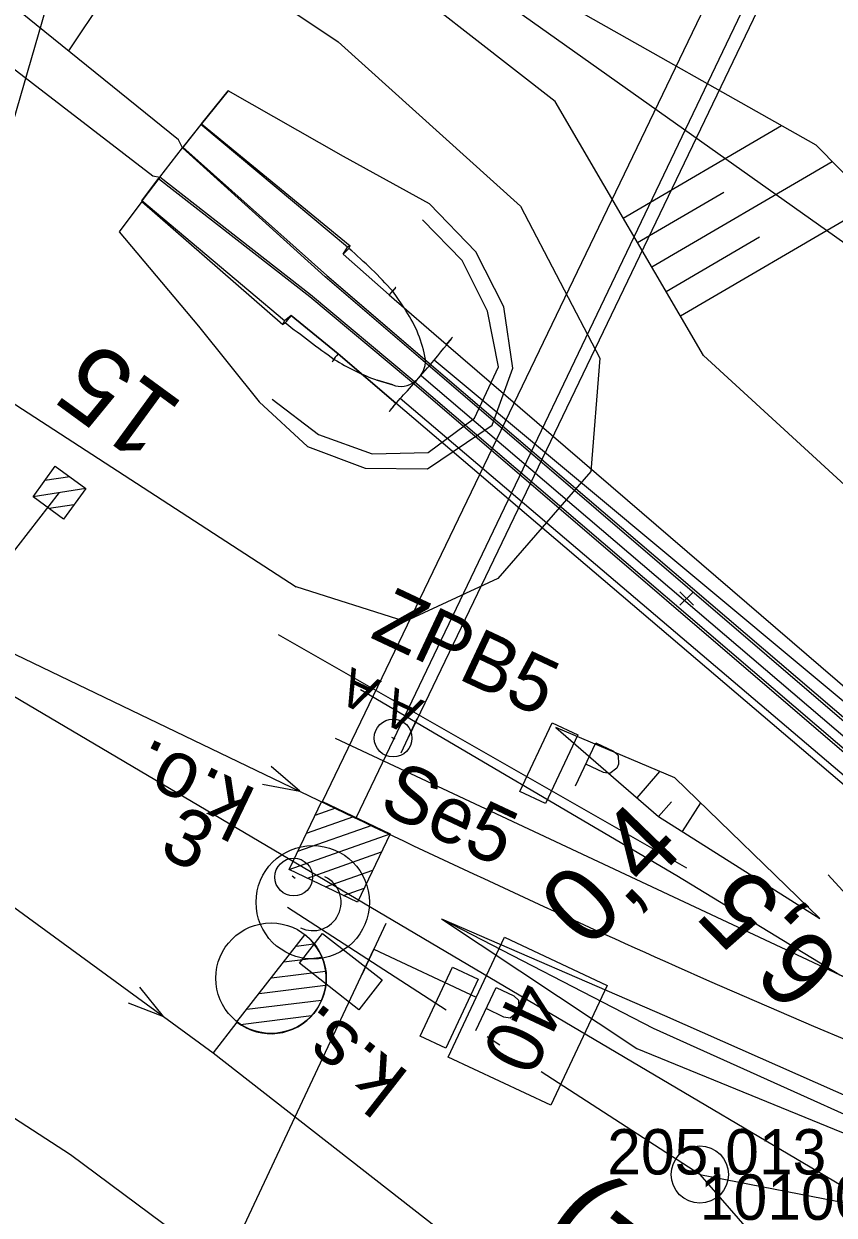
# Model space of a CAD drawing. Extents: x -800194 to -799078, y -1007177 to -1006597.
# Drawn here: x -799787.92 to -799766.47, y -1006976.93 to -1006945.41 of the extents above; entities that cross this region are included whole.
import ezdxf

# ---------------------------------------------------------------- set-up
doc = ezdxf.new("R2010")
doc.units = 0
for name, color, linetype in [('02_Osa_koleje', 7, 'Continuous'), ('_návrh', 7, 'Continuous'), ('_popvyt', 7, 'Continuous'), ('Vrstva 11', 7, 'Continuous'), ('Vrstva 13', 7, 'Continuous'), ('Vrstva 16', 7, 'Continuous'), ('Vrstva 17', 7, 'Continuous'), ('Vrstva 18', 7, 'Continuous'), ('Vrstva 2', 7, 'Continuous'), ('Vrstva 25', 7, 'Continuous'), ('Vrstva 27', 7, 'Continuous'), ('Vrstva 3', 7, 'Continuous'), ('Vrstva 34', 7, 'Continuous'), ('Vrstva 36', 7, 'Continuous'), ('Vrstva 4', 7, 'Continuous'), ('Vrstva 48', 7, 'Continuous'), ('Vrstva 49', 7, 'Continuous'), ('Vrstva 5', 7, 'Continuous'), ('Vrstva 55', 7, 'Continuous'), ('Vrstva 6', 7, 'Continuous'), ('Vrstva 60', 7, 'Continuous'), ('Vrstva 61', 7, 'Continuous'), ('Vrstva 63', 7, 'Continuous')]:
    doc.layers.add(name, color=color, linetype=linetype)

msp = doc.modelspace()

# ---------------------------------------------------------------- linework, layer by layer
at = {"layer": '02_Osa_koleje'}
msp.add_lwpolyline([(-799770.682, -1006970.328), (-799769.768, -1006970.733), (-799768.852, -1006971.134), (-799767.934, -1006971.532), (-799767.016, -1006971.927), (-799766.096, -1006972.319), (-799765.175, -1006972.709), (-799764.252, -1006973.095), (-799763.329, -1006973.478), (-799762.404, -1006973.858), (-799761.478, -1006974.235), (-799760.55, -1006974.609), (-799759.621, -1006974.98), (-799758.692, -1006975.348), (-799757.761, -1006975.713), (-799756.828, -1006976.075), (-799755.895, -1006976.434), (-799754.96, -1006976.789), (-799754.025, -1006977.142)], dxfattribs=at)
msp.add_arc((-799645.745, -1006688.806), 308, 244.32513, 246.06876, dxfattribs=at)
at = {"layer": '_návrh'}
msp.add_line((-799791.14, -1006960.652), (-799779.191, -1006966.397), dxfattribs=at)
for points in [[(-799821.595, -1006948.007), (-799811.064, -1006954.324), (-799803.753, -1006958.707), (-799793.935, -1006964.581), (-799784.224, -1006971.671), (-799782.913, -1006972.63), (-799767.418, -1006984.719), (-799752.333, -1006998.173), (-799735.027, -1007015.997), (-799721.623, -1007030.81), (-799713.555, -1007039.726), (-799713.111, -1007040.218)], [(-799820.755, -1006954.001), (-799803.004, -1006964.743), (-799786.682, -1006975.322), (-799769.882, -1006987.807), (-799754.745, -1007000.643), (-799736.311, -1007017.261), (-799721.623, -1007030.81)]]:
    msp.add_lwpolyline(points, dxfattribs=at)
msp.add_circle((-799780.274, -1006968.65), 1.5, dxfattribs=at)
for start, end in [(334.3251, 64.3251), (244.3251, 334.3251)]:
    msp.add_arc((-799780.274, -1006968.65), 0.75, start, end, dxfattribs=at)
at = {"layer": 'Vrstva 11'}
for p, q in [((-799786.705, -1006957.392), (-799787.366, -1006957.495)), ((-799801.01, -1006975.832), (-799786.978, -1006957.812)), ((-799786.281, -1006957.705), (-799787.674, -1006957.923)), ((-799786.594, -1006958.133), (-799787.246, -1006958.235))]:
    msp.add_line(p, q, dxfattribs=at)
msp.add_lwpolyline([(-799786.869, -1006958.511), (-799787.677, -1006957.921), (-799787.087, -1006957.113), (-799786.279, -1006957.703)], close=True, dxfattribs=at)
at = {"layer": 'Vrstva 16'}
for p, q in [((-799783.217, -1006948.059), (-799782.509, -1006947.186)), ((-799783.233, -1006948.077), (-799783.722, -1006948.693)), ((-799784.321, -1006949.462), (-799783.722, -1006948.693)), ((-799784.321, -1006949.462), (-799784.796, -1006950.091)), ((-799784.795, -1006950.113), (-799785.4, -1006950.909)), ((-799778.158, -1006952.483), (-799777.802, -1006953.01)), ((-799778.157, -1006954.96), (-799778.565, -1006954.841))]:
    msp.add_line(p, q, dxfattribs=at)
for points in [[(-799785.4, -1006950.909), (-799783.301, -1006953.407), (-799781.69, -1006955.406), (-799780.41, -1006956.591), (-799778.888, -1006957.162), (-799777.239, -1006957.179), (-799775.528, -1006956.024), (-799774.978, -1006954.519), (-799775.211, -1006952.901), (-799775.953, -1006951.439), (-799777.187, -1006950.172), (-799779.455, -1006948.919), (-799782.509, -1006947.186)], [(-799779.465, -1006951.506), (-799779.351, -1006951.322), (-799783.233, -1006948.077), (-799783.217, -1006948.059), (-799779.283, -1006951.287)], [(-799783.233, -1006948.077), (-799783.708, -1006948.669), (-799783.722, -1006948.693)], [(-799726.857, -1006999.659), (-799736.574, -1006991.623), (-799742.439, -1006986.725), (-799754.518, -1006974.879), (-799763.734, -1006965.993), (-799777.293, -1006954.374), (-799779.945, -1006952.099), (-799783.722, -1006948.693)], [(-799783.708, -1006948.669), (-799779.9, -1006952.065), (-799777.252, -1006954.333), (-799763.672, -1006965.935), (-799754.476, -1006974.829), (-799742.393, -1006986.703), (-799736.524, -1006991.578), (-799726.778, -1006999.642)], [(-799784.796, -1006950.091), (-799784.356, -1006949.5), (-799784.321, -1006949.462)], [(-799784.356, -1006949.5), (-799780.347, -1006952.62), (-799777.716, -1006954.827), (-799764.168, -1006966.436), (-799754.935, -1006975.363), (-799742.857, -1006987.188), (-799736.94, -1006992.081), (-799727.324, -1007000.028)], [(-799727.258, -1006999.988), (-799736.887, -1006992.032), (-799742.859, -1006987.132), (-799754.894, -1006975.337), (-799764.135, -1006966.374), (-799777.698, -1006954.783), (-799780.331, -1006952.581), (-799784.321, -1006949.462)], [(-799780.843, -1006953.125), (-799781.023, -1006953.264), (-799784.796, -1006950.091)], [(-799784.796, -1006950.091), (-799784.795, -1006950.113), (-799781.066, -1006953.365)], [(-799779.465, -1006951.506), (-799778.251, -1006952.583), (-799776.738, -1006953.884), (-799763.224, -1006965.504), (-799753.999, -1006974.421), (-799741.964, -1006986.204), (-799736.168, -1006991.012), (-799728.577, -1006997.215), (-799726.123, -1006999.163)], [(-799779.316, -1006951.352), (-799779.283, -1006951.287), (-799779.351, -1006951.322)], [(-799780.997, -1006953.316), (-799781.066, -1006953.365), (-799781.023, -1006953.264)], [(-799727.952, -1007000.326), (-799729.82, -1006998.717), (-799737.37, -1006992.486), (-799743.358, -1006987.594), (-799755.401, -1006975.883), (-799764.592, -1006966.926), (-799778.073, -1006955.449), (-799779.598, -1006954.142), (-799780.843, -1006953.125)]]:
    msp.add_lwpolyline(points, dxfattribs=at)
for centre, major_axis, ratio, start_param, end_param in [((-799780.763, -1006952.85), (1.448, 1.499), 0.000154, 0.037167, 0.458976), ((-799789.88, -1006959.484), (14.602, -0.402), 0.815768, 0.661553, 0.784611), ((-799780.886, -1006955.173), (2.894, 2.414), 0.919745, 5.794757, 6.192371), ((-799779.38, -1006951.872), (-1.627, -1.481), 0.054497, 5.778056, 6.111601), ((-799765.39, -1006947.43), (22.33, -7.783), 0.537883, 4.140419, 4.216217), ((-799775.114, -1006948.938), (-6.81, -2.765), 0.83994, 0.550611, 0.741846), ((-799777.883, -1006954.384), (0.368, 0.524), 0.895736, 3.328934, 5.426387)]:
    msp.add_ellipse(centre, major_axis=major_axis, ratio=ratio, start_param=start_param, end_param=end_param, dxfattribs=at)
at = {"layer": 'Vrstva 17'}
msp.add_line((-799766.63, -1006967.927), (-799764.528, -1006970.233), dxfattribs=at)
msp.add_lwpolyline([(-799781.343, -1006955.343), (-799780.121, -1006956.276), (-799778.697, -1006956.784), (-799777.217, -1006956.75), (-799775.995, -1006955.84), (-799775.356, -1006954.486), (-799775.648, -1006953.011), (-799776.321, -1006951.673), (-799777.368, -1006950.593)], dxfattribs=at)
at = {"layer": 'Vrstva 18'}
for p, q in [((-799778.158, -1006952.483), (-799777.802, -1006953.01)), ((-799778.565, -1006954.841), (-799778.157, -1006954.96))]:
    msp.add_line(p, q, dxfattribs=at)
for points in [[(-799779.465, -1006951.506), (-799778.251, -1006952.583), (-799776.738, -1006953.884)], [(-799780.843, -1006953.125), (-799779.598, -1006954.142), (-799778.073, -1006955.449)], [(-799776.738, -1006953.884), (-799763.224, -1006965.504), (-799753.999, -1006974.421), (-799741.964, -1006986.204), (-799736.168, -1006991.012)], [(-799728.689, -1006997.417), (-799736.272, -1006991.186), (-799742.111, -1006986.385), (-799754.178, -1006974.631), (-799763.368, -1006965.72), (-799777.061, -1006954.31)], [(-799736.701, -1006991.694), (-799742.573, -1006986.82), (-799754.68, -1006975.182), (-799763.887, -1006966.256), (-799777.391, -1006954.732)], [(-799737.37, -1006992.486), (-799743.358, -1006987.594), (-799755.401, -1006975.883), (-799764.592, -1006966.926), (-799778.073, -1006955.449)], [(-799729.664, -1006998.596), (-799737.245, -1006992.341), (-799743.186, -1006987.438), (-799755.222, -1006975.72), (-799764.444, -1006966.802), (-799777.959, -1006955.323)]]:
    msp.add_lwpolyline(points, dxfattribs=at)
for centre, major_axis, ratio, start_param, end_param in [((-799780.763, -1006952.85), (1.448, 1.499), 0.000154, 0.037167, 0.458976), ((-799789.88, -1006959.484), (14.602, -0.402), 0.815768, 0.661553, 0.784611), ((-799779.129, -1006954.252), (1.075, 1.846), 0.080877, 0.165328, 0.490733), ((-799779.092, -1006953.855), (1.015, 1.471), 0.015652, 6.081072, 6.66336), ((-799780.886, -1006955.173), (2.894, 2.414), 0.919745, 5.794757, 6.192371), ((-799779.38, -1006951.872), (-1.627, -1.481), 0.054497, 5.778056, 6.111601), ((-799765.39, -1006947.43), (22.33, -7.783), 0.537883, 4.140419, 4.216217), ((-799777.816, -1006955.165), (1.245, 1.471), 0.015308, 5.345189, 6.145729), ((-799777.816, -1006955.216), (1.244, 1.519), 0.010626, 6.159788, 6.793595), ((-799778.587, -1006952.902), (-1.171, -1.446), 0.009799, 6.046537, 6.582716), ((-799777.882, -1006953.279), (-1.858, -1.106), 0.135621, 5.801514, 6.067534), ((-799775.114, -1006948.938), (-6.81, -2.765), 0.83994, 0.550611, 0.741846), ((-799777.883, -1006954.384), (0.368, 0.524), 0.895736, 3.328934, 5.426387), ((-799777.417, -1006954.672), (0.706, 0.807), 0.030898, 3.802387, 5.20436), ((-799777.09, -1006954.29), (-1.161, -1.379), 0.000515, 6.0585, 7.007599), ((-799776.577, -1006954.198), (-1.666, -1.496), 0.062742, 5.768794, 6.060563)]:
    msp.add_ellipse(centre, major_axis=major_axis, ratio=ratio, start_param=start_param, end_param=end_param, dxfattribs=at)
at = {"layer": 'Vrstva 2'}
for p, q in [((-799756.904, -1006917.966), (-799780.025, -1006965.993)), ((-799782.282, -1006971.817), (-799780.481, -1006969.51)), ((-799780.715, -1006969.809), (-799780.242, -1006969.751)), ((-799781.042, -1006970.228), (-799780.034, -1006970.104)), ((-799781.368, -1006970.646), (-799779.935, -1006970.469)), ((-799781.695, -1006971.064), (-799779.932, -1006970.846)), ((-799782.021, -1006971.482), (-799780.038, -1006971.237)), ((-799782.188, -1006971.88), (-799780.304, -1006971.648)), ((-799782.283, -1006971.818), (-799782.913, -1006972.63)), ((-799782.282, -1006971.817), (-799782.282, -1006971.817))]:
    msp.add_line(p, q, dxfattribs=at)
for points in [[(-799781.6, -1006965.523), (-799780.617, -1006965.708), (-799781.376, -1006965.057)], [(-799785.157, -1006971.31), (-799784.224, -1006971.671), (-799784.852, -1006970.892)]]:
    msp.add_lwpolyline(points, dxfattribs=at)
msp.add_circle((-799781.376, -1006970.658), 1.462, dxfattribs=at)
msp.add_arc((-799781.382, -1006970.663), 1.464, 232.0587, 52.0195, dxfattribs=at)
at = {"layer": 'Vrstva 25'}
msp.add_lwpolyline([(-799778.434, -1006970.704), (-799779.049, -1006971.492), (-799780.626, -1006970.262), (-799780.011, -1006969.474), (-799778.434, -1006970.704)], dxfattribs=at)
at = {"layer": 'Vrstva 27'}
for p, q in [((-799778.191, -1006964.283), (-799778.101, -1006964.325)), ((-799780.817, -1006967.954), (-799780.737, -1006968.012))]:
    msp.add_line(p, q, dxfattribs=at)
for centre in [(-799778.146, -1006964.304), (-799780.777, -1006967.983)]:
    msp.add_circle(centre, 0.5, dxfattribs=at)
at = {"layer": 'Vrstva 3'}
for p, q in [((-799756.121, -1006918.343), (-799779.128, -1006966.408)), ((-799780.207, -1006966.345), (-799779.661, -1006966.153)), ((-799780.665, -1006967.302), (-799778.704, -1006966.611)), ((-799780.435, -1006966.823), (-799779.183, -1006966.382)), ((-799780.894, -1006967.78), (-799778.226, -1006966.84)), ((-799780.415, -1006968.009), (-799778.455, -1006967.318)), ((-799779.936, -1006968.238), (-799778.684, -1006967.797)), ((-799779.458, -1006968.467), (-799778.913, -1006968.275))]:
    msp.add_line(p, q, dxfattribs=at)
msp.add_lwpolyline([(-799780.03, -1006965.976), (-799778.226, -1006966.84), (-799779.09, -1006968.644), (-799780.894, -1006967.78)], close=True, dxfattribs=at)
at = {"layer": 'Vrstva 34'}
msp.add_line((-799781.191, -1006961.569), (-799770.384, -1006967.741), dxfattribs=at)
at = {"layer": 'Vrstva 36'}
for points in [[(-799773.933, -1006963.899), (-799773.259, -1006964.216), (-799774.115, -1006966.039), (-799774.789, -1006965.722)], [(-799776.571, -1006970.369), (-799775.897, -1006970.686), (-799776.753, -1006972.509), (-799777.427, -1006972.192)]]:
    msp.add_lwpolyline(points, close=True, dxfattribs=at)
for points in [[(-799773.318, -1006965.568), (-799772.784, -1006964.433), (-799772.312, -1006964.655), (-799772.192, -1006964.77), (-799772.178, -1006965), (-799772.225, -1006965.1), (-799772.413, -1006965.242), (-799772.576, -1006965.215), (-799773.048, -1006964.994)], [(-799775.956, -1006972.038), (-799775.422, -1006970.903), (-799774.95, -1006971.125), (-799774.83, -1006971.24), (-799774.816, -1006971.47), (-799774.863, -1006971.57), (-799775.051, -1006971.712), (-799775.214, -1006971.685), (-799775.686, -1006971.464)]]:
    msp.add_lwpolyline(points, dxfattribs=at)
at = {"layer": 'Vrstva 4'}
for points in [[(-799779.678, -1006964.304), (-799766.319, -1006970.565), (-799761.253, -1006973.176), (-799747.77, -1006978.421), (-799730.774, -1006983.8), (-799710.333, -1006988.709), (-799704.916, -1006989.741), (-799693.131, -1006991.407), (-799682.585, -1006992.929), (-799671.325, -1006993.879), (-799659.363, -1006994.45), (-799648.66, -1006994.501), (-799637.23, -1006994.127), (-799626.066, -1006993.335), (-799614.788, -1006992.17), (-799603.669, -1006990.506), (-799592.467, -1006988.452), (-799581.281, -1006985.916), (-799570.22, -1006982.998), (-799559.296, -1006979.606), (-799542.375, -1006973.485), (-799531.236, -1006968.774), (-799520.48, -1006963.762), (-799510.394, -1006958.536)], [(-799776.864, -1006969.085), (-799770.965, -1006971.646), (-799761.91, -1006975.649), (-799748.544, -1006980.777), (-799731.457, -1006986.215), (-799711.132, -1006991.054), (-799705.482, -1006992.16), (-799693.53, -1006994.084), (-799682.801, -1006995.384), (-799671.514, -1006996.319), (-799659.449, -1006996.851), (-799648.588, -1006996.949), (-799637.262, -1006996.573), (-799625.835, -1006995.773), (-799614.546, -1006994.586), (-799603.199, -1006992.945), (-799591.969, -1006990.857), (-799580.647, -1006988.335), (-799569.534, -1006985.311), (-799558.557, -1006981.947), (-799541.405, -1006975.739), (-799530.263, -1006971.071), (-799519.455, -1006966), (-799509.248, -1006960.724)], [(-799776.864, -1006969.085), (-799771.262, -1006971.982), (-799762.131, -1006976.093), (-799748.706, -1006981.286), (-799731.51, -1006986.353), (-799711.222, -1006991.459), (-799705.527, -1006992.587), (-799693.582, -1006994.543), (-799682.85, -1006995.904), (-799671.5, -1006996.805), (-799659.556, -1006997.356), (-799648.616, -1006997.341), (-799637.276, -1006997.071), (-799625.828, -1006996.297), (-799614.43, -1006995.109), (-799603.18, -1006993.475), (-799591.849, -1006991.264), (-799580.564, -1006988.698), (-799569.449, -1006985.746), (-799558.385, -1006982.386), (-799541.268, -1006976.227), (-799530.102, -1006971.505), (-799519.398, -1006966.36), (-799509.087, -1006961.127)], [(-799779.011, -1006963.023), (-799770.632, -1006967.944), (-799766.319, -1006970.565), (-799761.021, -1006972.82), (-799747.748, -1006977.966), (-799730.719, -1006983.271), (-799710.195, -1006988.108), (-799704.765, -1006989.181), (-799693.072, -1006990.965), (-799682.554, -1006992.238), (-799671.266, -1006993.222), (-799659.388, -1006993.765), (-799648.658, -1006993.824), (-799637.385, -1006993.531), (-799625.769, -1006992.728), (-799614.9, -1006991.542), (-799603.91, -1006989.963), (-799592.572, -1006987.892), (-799581.421, -1006985.419), (-799570.327, -1006982.332), (-799559.429, -1006979.066), (-799542.601, -1006973.013), (-799531.454, -1006968.25), (-799520.744, -1006963.214)], [(-799776.864, -1006969.085), (-799771.693, -1006972.522), (-799762.217, -1006976.394), (-799748.898, -1006981.647), (-799733.68, -1006986.66), (-799728.795, -1006987.945), (-799711.349, -1006992.599), (-799705.744, -1006994.116), (-799693.689, -1006996.09), (-799689.347, -1006996.226), (-799688.222, -1006996.296), (-799683.105, -1006997.407), (-799671.667, -1006998.275)]]:
    msp.add_lwpolyline(points, dxfattribs=at)
at = {"layer": 'Vrstva 48'}
for p, q in [((-799784.426, -1006942.662), (-799786.738, -1006946.125)), ((-799772.055, -1006950.547), (-799767.867, -1006948.1)), ((-799771.298, -1006951.842), (-799766.522, -1006949.052)), ((-799771.676, -1006951.195), (-799769.393, -1006949.861)), ((-799770.541, -1006953.137), (-799765.435, -1006950.154)), ((-799770.919, -1006952.49), (-799768.449, -1006951.046)), ((-799771.688, -1006965.89), (-799771.083, -1006965.192)), ((-799771.121, -1006966.381), (-799770.781, -1006965.989)), ((-799770.486, -1006966.781), (-799770.005, -1006966.018))]:
    msp.add_line(p, q, dxfattribs=at)
at = {"layer": 'Vrstva 49'}
for p, q in [((-799770.553, -1006960.435), (-799770.199, -1006960.789)), ((-799770.553, -1006960.789), (-799770.199, -1006960.435))]:
    msp.add_line(p, q, dxfattribs=at)
for points in [[(-799783.829, -1006948.476), (-799791.557, -1006942.231), (-799800.207, -1006931.486), (-799804.329, -1006925.793)], [(-799804.932, -1006926.453), (-799801.356, -1006932.305), (-799792.538, -1006943.25), (-799784.51, -1006949.428)], [(-799787.714, -1006940.466), (-799779.601, -1006945.884), (-799774.772, -1006950.23), (-799772.678, -1006954.259), (-799772.914, -1006957.256), (-799775.374, -1006960.084), (-799777.823, -1006961.225), (-799780.709, -1006960.303)], [(-799809.896, -1006941.363), (-799780.709, -1006960.303)], [(-799777.554, -1006942.387), (-799773.745, -1006944.786), (-799766.953, -1006948.615), (-799760.613, -1006955.042), (-799758.076, -1006961.72), (-799756.886, -1006965.592)], [(-799760.173, -1006964.364), (-799762.769, -1006960.758), (-799769.93, -1006954.183), (-799773.856, -1006947.464), (-799779.16, -1006943.327)], [(-799784.51, -1006949.428), (-799784.321, -1006949.462), (-799784.796, -1006950.091), (-799784.795, -1006950.113), (-799785.4, -1006950.909), (-799783.301, -1006953.407), (-799781.69, -1006955.406), (-799780.41, -1006956.591), (-799778.888, -1006957.162), (-799777.239, -1006957.179), (-799775.528, -1006956.024), (-799774.978, -1006954.519), (-799775.211, -1006952.901), (-799775.953, -1006951.439), (-799777.187, -1006950.172), (-799779.455, -1006948.919), (-799782.509, -1006947.186), (-799783.217, -1006948.059), (-799783.233, -1006948.077), (-799783.722, -1006948.693), (-799783.829, -1006948.476)], [(-799773.843, -1006964.024), (-799771.12, -1006966.382), (-799766.849, -1006969.075)], [(-799766.849, -1006969.075), (-799770.685, -1006965.36), (-799773.843, -1006964.024)]]:
    msp.add_lwpolyline(points, dxfattribs=at)
at = {"layer": 'Vrstva 5'}
for p, q in [((-799778.34, -1006969.207), (-799778.978, -1006970.565)), ((-799796.24, -1007007.322), (-799778.659, -1006969.886)), ((-799778.659, -1006969.886), (-799775.944, -1006971.161))]:
    msp.add_line(p, q, dxfattribs=at)
msp.add_lwpolyline([(-799776.687, -1006972.745), (-799775.2, -1006969.577), (-799772.484, -1006970.853), (-799773.972, -1006974.021)], close=True, dxfattribs=at)
at = {"layer": 'Vrstva 55'}
msp.add_line((-799785.23, -1006937.71), (-799741.57, -1006968.68), dxfattribs=at)
msp.add_lwpolyline([(-799785.23, -1006937.71), (-799791.69, -1006959.99), (-799791.97, -1006960.97), (-799746.76, -1006987.67), (-799745.68, -1006988.03), (-799733.28, -1006992.13)], dxfattribs=at)
at = {"layer": 'Vrstva 6'}
msp.add_line((-799777.933, -1006964.695), (-799777.507, -1006963.789), dxfattribs=at)
msp.add_lwpolyline([(-799752.416, -1006919.71), (-799759.639, -1006934.751), (-799762.823, -1006933.223), (-799777.74, -1006964.286)], dxfattribs=at)
at = {"layer": 'Vrstva 60'}
msp.add_line((-799770.028, -1006975.851), (-799770.028, -1006975.851), dxfattribs=at)
at = {"layer": 'Vrstva 63'}
for p, q in [((-799776.745, -1006971.506), (-799780.943, -1006968.79)), ((-799775.318, -1006972.429), (-799775.653, -1006972.212)), ((-799770.028, -1006975.851), (-799774.226, -1006973.135)), ((-799769.989, -1006975.882), (-799770.067, -1006975.82)), ((-799770.028, -1006975.851), (-799765.12, -1006976.804)), ((-799770.028, -1006975.851), (-799766.738, -1006979.616))]:
    msp.add_line(p, q, dxfattribs=at)
msp.add_circle((-799770.028, -1006975.851), 0.756, dxfattribs=at)

# ---------------------------------------------------------------- texts
at = {"layer": '_popvyt'}
msp.add_text('3', height=1.5, rotation=334.3251, dxfattribs=at).set_placement((-799784.386, -1006967.382))
at = {"layer": 'Vrstva 11'}
msp.add_text('15', height=2, rotation=143.8668, dxfattribs=at).set_placement((-799783.638, -1006955.492))
at = {"layer": 'Vrstva 13'}
msp.add_text('6,5', height=2, rotation=134.4646, dxfattribs=at).set_placement((-799766.184, -1006970.262))
at = {"layer": 'Vrstva 25'}
msp.add_text('k.s.', height=1.5, rotation=142.0391, dxfattribs=at).set_placement((-799777.68, -1006973.186))
at = {"layer": 'Vrstva 27'}
for s, rotation, p in [('ZPB5', 334.8436, (-799778.789, -1006961.631)), ('k.o.', 154.3489, (-799781.715, -1006965.686))]:
    msp.add_text(s, height=1.5, rotation=rotation, dxfattribs=at).set_placement(p)
at = {"layer": 'Vrstva 48'}
msp.add_text('0,4', height=2, rotation=45.9181, dxfattribs=at).set_placement((-799772.985, -1006969.943))
at = {"layer": 'Vrstva 5'}
msp.add_text('40', height=1.5, rotation=244.8436, dxfattribs=at).set_placement((-799774.876, -1006970.653))
at = {"layer": 'Vrstva 6'}
for s, height, rotation, p in [('A A ', 1, 154.8436, (-799777.295, -1006963.337)), ('Se5', 1.5, 334.8436, (-799778.573, -1006966.216))]:
    msp.add_text(s, height=height, rotation=rotation, dxfattribs=at).set_placement(p)
at = {"layer": 'Vrstva 60'}
msp.add_text('10100003830', height=1.2, dxfattribs=at).set_placement((-799770.028, -1006977.051))
at = {"layer": 'Vrstva 61'}
msp.add_text('205.013', height=1.2, dxfattribs=at).set_placement((-799772.48, -1006975.851))
at = {"layer": 'Vrstva 63'}
msp.add_text('(TÚ 0101)', height=2.4, rotation=142.0391, dxfattribs=at).set_placement((-799761.816, -1006984.928))

doc.saveas('drawing.dxf')
